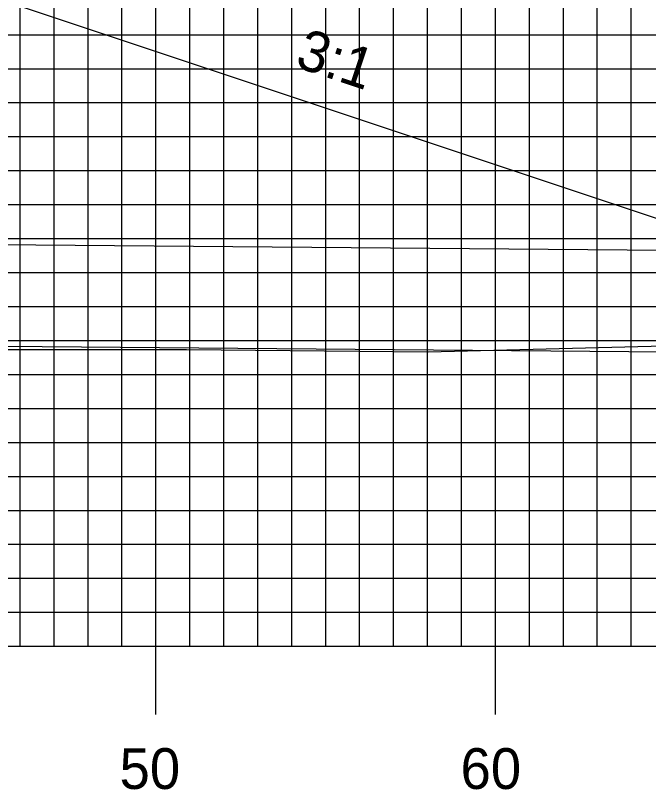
# Model space of a CAD drawing. Extents: x 1781467 to 1781810, y 442591 to 442811.
# Drawn here: x 1781678.27 to 1781696.92, y 442659.45 to 442682.23 of the extents above; entities that cross this region are included whole.
import ezdxf

# ---------------------------------------------------------------- set-up
doc = ezdxf.new("R2010")
doc.units = 0
for name, color, linetype in [('ANNOTATION', 7, 'Continuous'), ('D_Drainage_Culvert', 7, 'Continuous'), ('D_Roadway_Centerline', 7, 'Continuous'), ('D_Roadway_SlopeLines', 7, 'Continuous'), ('H_V ANNOTATION', 7, 'Continuous'), ('MAJOR', 7, 'Continuous'), ('MINOR', 7, 'Continuous'), ('S_Roadway_Centerline', 7, 'Continuous')]:
    doc.layers.add(name, color=color, linetype=linetype)

msp = doc.modelspace()

# ---------------------------------------------------------------- linework, layer by layer
at = {"layer": 'D_Drainage_Culvert'}
msp.add_lwpolyline([(1781561.558, 442673.475), (1781561.583, 442676.475), (1781705.578, 442675.25), (1781705.553, 442672.25)], close=True, dxfattribs=at)
at = {"layer": 'D_Roadway_Centerline'}
msp.add_lwpolyline([(1781570.792, 442677.306), (1781600.408, 442687.178), (1781602.234, 442687.634), (1781612.408, 442690.178), (1781620.408, 442690.498), (1781632.408, 442690.738), (1781644.408, 442690.498), (1781652.408, 442690.178), (1781662.582, 442687.634), (1781664.408, 442687.178), (1781697.344, 442676.199)], dxfattribs=at)
at = {"layer": 'D_Roadway_SlopeLines'}
msp.add_lwpolyline([(1781652.408, 442690.178), (1781664.408, 442687.178), (1781697.344, 442676.199)], dxfattribs=at)
at = {"layer": 'MAJOR'}
for p, q in [((1781682.408, 442663.665), (1781682.408, 442698.665)), ((1781692.408, 442663.665), (1781692.408, 442698.665)), ((1781492.408, 442678.665), (1781772.408, 442678.665)), ((1781492.408, 442673.665), (1781772.408, 442673.665)), ((1781492.408, 442668.665), (1781772.408, 442668.665)), ((1781492.408, 442663.665), (1781772.408, 442663.665)), ((1781492.408, 442663.665), (1781772.408, 442663.665)), ((1781682.408, 442661.661), (1781682.408, 442663.665)), ((1781692.408, 442661.661), (1781692.408, 442663.665))]:
    msp.add_line(p, q, dxfattribs=at)
at = {"layer": 'MINOR'}
for p, q in [((1781678.408, 442663.665), (1781678.408, 442698.665)), ((1781679.408, 442663.665), (1781679.408, 442698.665)), ((1781680.408, 442663.665), (1781680.408, 442698.665)), ((1781681.408, 442663.665), (1781681.408, 442698.665)), ((1781683.408, 442663.665), (1781683.408, 442698.665)), ((1781684.408, 442663.665), (1781684.408, 442698.665)), ((1781685.408, 442663.665), (1781685.408, 442698.665)), ((1781686.408, 442663.665), (1781686.408, 442698.665)), ((1781687.408, 442663.665), (1781687.408, 442698.665)), ((1781688.408, 442663.665), (1781688.408, 442698.665)), ((1781689.408, 442663.665), (1781689.408, 442698.665)), ((1781690.408, 442663.665), (1781690.408, 442698.665)), ((1781691.408, 442663.665), (1781691.408, 442698.665)), ((1781693.408, 442663.665), (1781693.408, 442698.665)), ((1781694.408, 442663.665), (1781694.408, 442698.665)), ((1781695.408, 442663.665), (1781695.408, 442698.665)), ((1781696.408, 442663.665), (1781696.408, 442698.665)), ((1781492.408, 442681.665), (1781772.408, 442681.665)), ((1781492.408, 442680.665), (1781772.408, 442680.665)), ((1781492.408, 442679.665), (1781772.408, 442679.665)), ((1781492.408, 442677.665), (1781772.408, 442677.665)), ((1781492.408, 442676.665), (1781772.408, 442676.665)), ((1781492.408, 442675.665), (1781772.408, 442675.665)), ((1781492.408, 442674.665), (1781772.408, 442674.665)), ((1781492.408, 442672.665), (1781772.408, 442672.665)), ((1781492.408, 442671.665), (1781772.408, 442671.665)), ((1781492.408, 442670.665), (1781772.408, 442670.665)), ((1781492.408, 442669.665), (1781772.408, 442669.665)), ((1781492.408, 442667.665), (1781772.408, 442667.665)), ((1781492.408, 442666.665), (1781772.408, 442666.665)), ((1781492.408, 442665.665), (1781772.408, 442665.665)), ((1781492.408, 442664.665), (1781772.408, 442664.665))]:
    msp.add_line(p, q, dxfattribs=at)
at = {"layer": 'S_Roadway_Centerline'}
msp.add_lwpolyline([(1781598.923, 442672.598), (1781605.769, 442672.682), (1781612.104, 442672.616), (1781618.641, 442672.529), (1781638.856, 442672.721), (1781640.791, 442672.69), (1781642.594, 442672.718), (1781663.6, 442672.44), (1781666.446, 442672.399), (1781683.308, 442672.4), (1781690.428, 442672.33), (1781698.54, 442672.537), (1781707.774, 442672.208), (1781713.19, 442672.208), (1781731.44, 442672.192), (1781734.769, 442672.21), (1781754.689, 442673.378), (1781757.057, 442673.385), (1781767.785, 442672.274), (1781772.408, 442672.229)], dxfattribs=at)

# ---------------------------------------------------------------- texts
at = {"layer": 'ANNOTATION'}
msp.add_text('3:1', height=1.2, rotation=341.5652, dxfattribs=at).set_placement((1781686.466, 442680.733))
at = {"layer": 'H_V ANNOTATION'}
for s, p in [('50', (1781681.337, 442659.465)), ('60', (1781691.38, 442659.465))]:
    msp.add_text(s, height=1.2, dxfattribs=at).set_placement(p)

doc.saveas('drawing.dxf')
